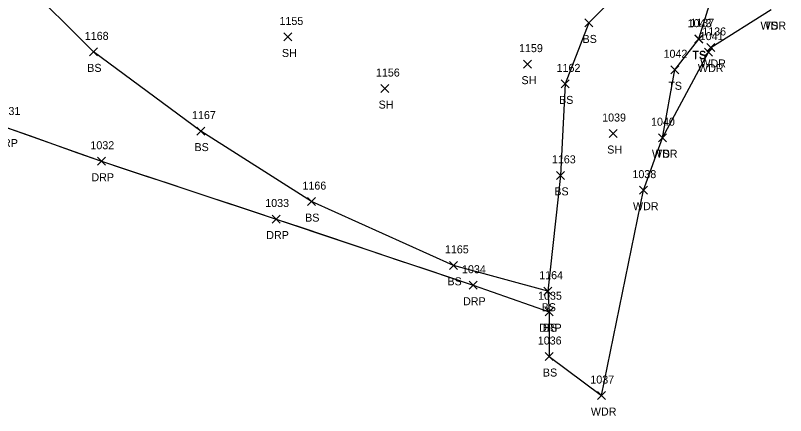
# Model space of a CAD drawing. Extents: x 1639430 to 1640195, y 612006 to 612917.
# Drawn here: x 1639980.2 to 1640172.6, y 612401.1 to 612501.1 of the extents above; entities that cross this region are included whole.
import ezdxf

# ---------------------------------------------------------------- set-up
doc = ezdxf.new("R2010")
doc.units = 0
for name, color, linetype in [('L_A', 7, 'Continuous'), ('L_I', 7, 'Continuous'), ('L_TIC', 7, 'Continuous'), ('LAWA', 7, 'Continuous'), ('LELB', 7, 'Continuous'), ('LSOGP', 7, 'Continuous'), ('R_A', 7, 'Continuous'), ('R_I', 7, 'Continuous'), ('R_TIC', 7, 'Continuous'), ('RDP', 7, 'Continuous')]:
    doc.layers.add(name, color=color, linetype=linetype)

msp = doc.modelspace()

# ---------------------------------------------------------------- linework, layer by layer
at = {"layer": 'L_TIC'}
for points in [[(1640122.47, 612498.22), (1640124.47, 612500.22)], [(1640124.47, 612498.22), (1640122.47, 612500.22)], [(1640047.3, 612494.71), (1640049.3, 612496.71)], [(1640049.3, 612494.71), (1640047.3, 612496.71)], [(1640149.93, 612494.15), (1640151.93, 612496.15)], [(1640151.93, 612494.15), (1640149.93, 612496.15)], [(1640149.98, 612494.27), (1640151.98, 612496.27)], [(1640151.98, 612494.27), (1640149.98, 612496.27)], [(1640153, 612492.09), (1640155, 612494.09)], [(1640155, 612492.09), (1640153, 612494.09)], [(1639998.71, 612490.99), (1640000.71, 612492.99)], [(1640000.71, 612490.99), (1639998.71, 612492.99)], [(1640152.39, 612490.92), (1640154.39, 612492.92)], [(1640154.39, 612490.92), (1640152.39, 612492.92)], [(1640107.18, 612487.92), (1640109.18, 612489.92)], [(1640109.18, 612487.92), (1640107.18, 612489.92)], [(1640143.93, 612486.52), (1640145.93, 612488.52)], [(1640145.93, 612486.52), (1640143.93, 612488.52)], [(1640116.6, 612482.99), (1640118.6, 612484.99)], [(1640118.6, 612482.99), (1640116.6, 612484.99)], [(1640071.47, 612481.82), (1640073.47, 612483.82)], [(1640073.47, 612481.82), (1640071.47, 612483.82)], [(1640025.5, 612471.2), (1640027.5, 612473.2)], [(1640027.5, 612471.2), (1640025.5, 612473.2)], [(1640128.59, 612470.59), (1640130.59, 612472.59)], [(1640130.59, 612470.59), (1640128.59, 612472.59)], [(1640140.89, 612469.54), (1640142.89, 612471.54)], [(1640142.89, 612469.54), (1640140.89, 612471.54)], [(1640140.89, 612469.54), (1640142.89, 612471.54)], [(1640142.89, 612469.54), (1640140.89, 612471.54)], [(1640115.42, 612460.14), (1640117.42, 612462.14)], [(1640117.42, 612460.14), (1640115.42, 612462.14)], [(1640136.15, 612456.44), (1640138.15, 612458.44)], [(1640138.15, 612456.44), (1640136.15, 612458.44)], [(1640053.14, 612453.58), (1640055.14, 612455.58)], [(1640055.14, 612453.58), (1640053.14, 612455.58)], [(1640088.7, 612437.66), (1640090.7, 612439.66)], [(1640090.7, 612437.66), (1640088.7, 612439.66)], [(1640112.26, 612431.2), (1640114.26, 612433.2)], [(1640114.26, 612431.2), (1640112.26, 612433.2)], [(1640112.57, 612426.07), (1640114.57, 612428.07)], [(1640114.57, 612426.07), (1640112.57, 612428.07)], [(1640112.56, 612414.88), (1640114.56, 612416.88)], [(1640114.56, 612414.88), (1640112.56, 612416.88)], [(1640125.63, 612405.13), (1640127.63, 612407.13)], [(1640127.63, 612405.13), (1640125.63, 612407.13)]]:
    msp.add_lwpolyline(points, dxfattribs=at)
at = {"layer": 'LAWA'}
msp.add_lwpolyline([(1640126.63, 612406.13), (1640137.15, 612457.44), (1640141.89, 612470.54), (1640153.39, 612491.92), (1640154, 612493.09), (1640169.02, 612502.55)], dxfattribs=at)
at = {"layer": 'LELB'}
for points in [[(1640141.89, 612470.54), (1640144.93, 612487.52), (1640150.93, 612495.15), (1640150.98, 612495.27), (1640154.78, 612507.63), (1640148.01, 612518.42), (1640138.28, 612525.74), (1640128.68, 612534.49), (1640123.09, 612541.89), (1640122.91, 612554.41), (1640125.68, 612564.51), (1640122.4, 612566.25), (1640119.66, 612562.41), (1640114.78, 612563.84), (1640105.62, 612570.37), (1640091.61, 612592.16)], [(1640140.23, 612516.27), (1640123.47, 612499.22), (1640117.6, 612483.99), (1640116.42, 612461.14), (1640113.26, 612432.2), (1640089.7, 612438.66), (1640054.14, 612454.58), (1640026.5, 612472.2), (1639999.71, 612491.99), (1639981.61, 612510.09)], [(1640113.26, 612432.2), (1640113.57, 612427.07)], [(1640113.57, 612427.07), (1640113.56, 612415.88)]]:
    msp.add_lwpolyline(points, dxfattribs=at)
at = {"layer": 'LSOGP'}
msp.add_lwpolyline([(1639977.68, 612473.21), (1639983.69, 612471.07), (1639989.69, 612468.93), (1639995.7, 612466.79), (1640001.7, 612464.66), (1640007.16, 612462.85), (1640012.62, 612461.05), (1640018.09, 612459.25), (1640023.55, 612457.44), (1640029.01, 612455.64), (1640034.47, 612453.84), (1640039.93, 612452.03), (1640045.39, 612450.23), (1640051.54, 612448.16), (1640057.69, 612446.1), (1640063.83, 612444.03), (1640069.98, 612441.96), (1640076.12, 612439.89), (1640082.27, 612437.83), (1640088.42, 612435.76), (1640094.56, 612433.69), (1640099.31, 612432.04), (1640104.07, 612430.38), (1640108.82, 612428.72), (1640113.57, 612427.07), (1640113.56, 612415.88), (1640126.63, 612406.13), (1640137.15, 612457.44), (1640141.89, 612470.54), (1640153.39, 612491.92), (1640154, 612493.09), (1640169.02, 612502.55)], dxfattribs=at)
at = {"layer": 'R_TIC'}
for points in [[(1640000.7, 612463.66), (1640002.7, 612465.66)], [(1640002.7, 612463.66), (1640000.7, 612465.66)], [(1640044.39, 612449.23), (1640046.39, 612451.23)], [(1640046.39, 612449.23), (1640044.39, 612451.23)], [(1640093.56, 612432.69), (1640095.56, 612434.69)], [(1640095.56, 612432.69), (1640093.56, 612434.69)], [(1640112.57, 612426.07), (1640114.57, 612428.07)], [(1640114.57, 612426.07), (1640112.57, 612428.07)]]:
    msp.add_lwpolyline(points, dxfattribs=at)
at = {"layer": 'RDP'}
msp.add_lwpolyline([(1639791.07, 612492.27), (1639790.56, 612482.42), (1639792.35, 612472.77), (1639797.16, 612465.25), (1639817.68, 612451.17), (1639836.4, 612438.97), (1639858.15, 612425.17), (1639868.59, 612420.18), (1639882.11, 612420.19), (1639897.25, 612425.27), (1639908.83, 612433.43), (1639923.77, 612450.11), (1639940.54, 612474.05), (1639946.23, 612483.43), (1639977.68, 612473.21), (1640001.7, 612464.66), (1640045.39, 612450.23), (1640094.56, 612433.69), (1640113.57, 612427.07)], dxfattribs=at)

# ---------------------------------------------------------------- texts
at = {"layer": 'L_A'}
for s, p in [('WDR', (1640166.38, 612497.55)), ('TS', (1640167.43, 612497.55)), ('BS', (1640121.91, 612494.22)), ('SH', (1640046.79, 612490.71)), ('TS', (1640149.34, 612490.15)), ('TS', (1640149.39, 612490.27)), ('WDR', (1640151.36, 612488.09)), ('BS', (1639998.15, 612486.99)), ('WDR', (1640150.75, 612486.92)), ('SH', (1640106.66, 612483.92)), ('TS', (1640143.34, 612482.52)), ('BS', (1640116.04, 612478.99)), ('SH', (1640070.95, 612477.82)), ('BS', (1640024.94, 612467.2)), ('SH', (1640128.07, 612466.59)), ('WDR', (1640139.25, 612465.54)), ('TS', (1640140.29, 612465.54)), ('BS', (1640114.86, 612456.14)), ('WDR', (1640134.51, 612452.44)), ('BS', (1640052.59, 612449.58)), ('BS', (1640088.14, 612433.66)), ('BS', (1640111.7, 612427.2)), ('BS', (1640112.01, 612422.07)), ('BS', (1640112, 612410.88)), ('WDR', (1640123.99, 612401.13))]:
    msp.add_text(s, height=2, dxfattribs=at).set_placement(p)
at = {"layer": 'L_I'}
for s, p in [('1155', (1640046.18, 612498.71)), ('1043', (1640148.16, 612498.15)), ('1137', (1640148.86, 612498.27)), ('1136', (1640151.82, 612496.09)), ('1168', (1639997.53, 612494.99)), ('1041', (1640151.19, 612494.92)), ('1159', (1640106.04, 612491.92)), ('1042', (1640142.15, 612490.52)), ('1162', (1640115.42, 612486.99)), ('1156', (1640070.28, 612485.82)), ('1167', (1640024.32, 612475.2)), ('1039', (1640126.81, 612474.59)), ('1040', (1640139.03, 612473.54)), ('1040', (1640139.03, 612473.54)), ('1163', (1640114.25, 612464.14)), ('1038', (1640134.38, 612460.44)), ('1166', (1640051.92, 612457.58)), ('1165', (1640087.52, 612441.66)), ('1164', (1640111.08, 612435.2)), ('1035', (1640110.8, 612430.07)), ('1036', (1640110.73, 612418.88)), ('1037', (1640123.86, 612409.13))]:
    msp.add_text(s, height=2, dxfattribs=at).set_placement(p)
at = {"layer": 'R_A'}
for p in [(1639975.17, 612468.21), (1639999.19, 612459.66), (1640042.88, 612445.23), (1640092.05, 612428.69), (1640111.06, 612422.07)]:
    msp.add_text('DRP', height=2, dxfattribs=at).set_placement(p)
at = {"layer": 'R_I'}
for s, p in [('1031', (1639975.48, 612476.21)), ('1032', (1639998.93, 612467.66)), ('1033', (1640042.62, 612453.23)), ('1034', (1640091.79, 612436.69)), ('1035', (1640110.8, 612430.07))]:
    msp.add_text(s, height=2, dxfattribs=at).set_placement(p)

doc.saveas('drawing.dxf')
